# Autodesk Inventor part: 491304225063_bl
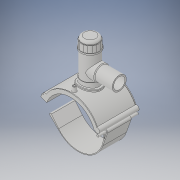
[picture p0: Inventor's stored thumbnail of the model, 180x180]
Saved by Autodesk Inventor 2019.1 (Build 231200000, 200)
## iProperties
Created: 2017-07
Part Number: 491304225063_bl
Material: Generic
Description: PLASSON TAPPING TEE SADDLE 225mm x 63mm
Document SubType Name: Modeling
Designer: KIM
Mass: 1712.7 g
Surface Area: 2671.49 cm^2
Volume: 1712.7 cm^3
Density: 1 g/cm^3
Appearance: Default
Author: KIM
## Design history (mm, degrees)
derived "491304.ipt"
feature "Solid1::491304.ipt" dims "ScaleForDerivedMember" = 10
feature "Solid2::491304.ipt" dims "ScaleForDerivedMember" = 10
feature "Solid4::491304.ipt" dims "ScaleForDerivedMember" = 10
feature "Solid5::491304.ipt" dims "ScaleForDerivedMember" = 10
tag "TaggingFeature1"
body "Solid1"
body "Solid2"
other parameters: "d0" = 225 [user parameter], "d1" = 101.118 [user parameter], "d2" = 288 [user parameter], "d3" = 56.25 [user parameter], "d4" = 176 [user parameter], "d5" = 0 [user parameter], "d6" = 0.1 [user parameter], "d8" = 0 [user parameter], "d40" = 135 [user parameter], "d41" = 97.65 [user parameter], "d43" = 0 [user parameter], "d45" = 0 [user parameter], "d47" = 156.159 [user parameter], "d78" = 147.5 [user parameter], "d79" = 15 [user parameter], "d80" = 70.4 [user parameter], "d82" = 5 deg [user parameter], "d84" = 4 [user parameter], "d85" = 14 [user parameter], "d86" = 0 [user parameter], "d87" = 3 [user parameter], "d88" = 0 [user parameter], "d97" = 3.52 [user parameter], "d98" = 0 [user parameter], "d102" = 2.25 [user parameter], "d120" = 140 deg [user parameter], "d123" = 606.708 [user parameter], "d126" = 0 [user parameter], "d153" = 176 [user parameter], "d154" = 0 [user parameter], "d159" = -24.7764 [user parameter], "d162" = 105.6 [user parameter], "d163" = 0 [user parameter], "d164" = 112.5 [user parameter], "d169" = 4.0905 [user parameter], "d172" = 0 [user parameter], "d173" = 1 [user parameter], "d175" = 112.5 [user parameter], "d176" = 20 deg [user parameter], "d177" = 15.75 [user parameter], "d180" = 0 [user parameter], "d184" = 12.6 [user parameter], "d187" = 123.75 [user parameter], "d188" = 15 [user parameter], "d189" = 15.75 [user parameter], "d190" = 0 [user parameter], "d191" = 168.75 [user parameter], "d195" = 90 deg [user parameter], "d197" = 0 [user parameter], "d199" = 0 [user parameter], "d200" = 15.75 [user parameter], "d202" = 0 [user parameter], "d203" = 195 [user parameter], "d206" = 75.6 [user parameter], "d207" = 146.25 [user parameter], "d208" = 152.1 [user parameter], "d209" = 181.35 [user parameter], "d210" = 76.86 [user parameter], "d212" = 72.45 [user parameter], "d213" = 39.15 [user parameter], "d216" = 0 [user parameter], "d217" = 22.5 [user parameter], "d218" = 11.25 [user parameter], "d219" = 2.25 [user parameter], "d222" = 225 [user parameter], "d224" = 0 [user parameter], "d259" = 50.4 [user parameter], "d260" = 63 [user parameter], "d265" = 0 [user parameter], "d267" = 13.00006 [user parameter], "d268" = 2.60001 [user parameter], "d269" = 2.60001 [user parameter], "d271" = 2.60001 [user parameter], "d273" = 0 [user parameter], "d274" = 23.56194 [user parameter], "d280" = 0 [user parameter], "d281" = 225 [user parameter], "d283" = 0 [user parameter], "d285" = 0 [user parameter], "d290" = 22.5 [user parameter], "d293" = 123.75 [user parameter], "d294" = 115.875 [user parameter], "d296" = 33.75 [user parameter], "d299" = 75 [user parameter], "d300" = 3 [user parameter], "d301" = 5 [user parameter], "d303" = 81.9 [user parameter], "d304" = 69.3 [user parameter], "d305" = 45 deg [user parameter], "d306" = 50.4 [user parameter], "d307" = 140.625 [user parameter], "d308" = 135 [user parameter], "d309" = 1125 [user parameter], "d310" = 1 [user parameter], "d314" = 675 [user parameter], "d" = 225 [user parameter], "L" = 176 [user parameter], "d_t" = 6 [user parameter], "H2" = 195 [user parameter], "H1" = 75 [user parameter], "d_1" = 63 [user parameter]
